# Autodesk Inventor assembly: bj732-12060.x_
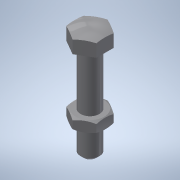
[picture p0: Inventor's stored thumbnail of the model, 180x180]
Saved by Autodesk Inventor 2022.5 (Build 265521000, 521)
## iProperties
Part Number: bj732-12060.x_
Material: 一般
Document SubType Name: Assembly
Designer: ImaoCorp
Sending System: SOLIDWORKS 2017-2017317
MC: AMD64
MC_MODEL: Intel64 Family 6 Model 60 Stepping 3, GenuineIntel
OS: Windows_NT
FRU: Parasolid Version 29.0, build 201,  4-17-2017
FORMAT: text
GUISE: transmit
KEY: bj732-12060
FILE: bj732-12060.x_t
DATE: Fri Mar 15 10:10:31 2019
Author: ImaoCorp
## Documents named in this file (3)
- X:\14_SW2022-Inv2022\00_全2023-1023新製品(TCC)まで\b\bj732-12060\BJ732-12060.iam
- X:\14_SW2022-Inv2022\00_全2023-1023新製品(TCC)まで\b\bj732-12060\bj732-12060_01.ipt
- X:\14_SW2022-Inv2022\00_全2023-1023新製品(TCC)まで\b\bj732-12060\bj732-12060_02.ipt
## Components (2 placed, 2 different names)
1. bj732-12060_01
2. bj732-12060_02
